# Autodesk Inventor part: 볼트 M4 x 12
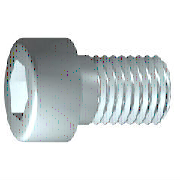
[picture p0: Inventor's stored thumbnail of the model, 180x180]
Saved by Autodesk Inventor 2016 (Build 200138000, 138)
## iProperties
IsCustomPart: 1
Created: 2012-02
Part Number: 볼트 M4 x 12
Material: 스테인리스강
Description: 6각 소켓 머리 캡 나사
Document SubType Name: Modeling
Standard: ISO 4762
Designer: mduedu
Standard Revision: Fourth edition 2004-03-01
Standards Organization: ISO
Language: ko-KR
Size Designation: M4 x 12
Categories: <MemberInstance><Categories><Category DisplayName="조임쇠" InternalName="e4da775c-781d-43d5-af7c-5136215cf5a6" Mnemonic="FSTN"><Category DisplayName="볼트" InternalN
Density: 8.08 g/cm^3
Appearance: 반광택
Author: mduedu
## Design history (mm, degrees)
sketch "스케치1"
  geometry: L1 (-1, 0)-(12, 0); L2 (12, 0)-(12, 2); L3 (12, 2)-(1.75, 2); L4 (1.75, 2)-(1.32, 2); L5 (1.32, 2)-(0, 2); L6 (0, 2)-(0, 3.5); L7 (0, 3.5)-(-4, 3.5); L8 (-4, 3.5)-(-4, 1.732); L9 (-4, 1.732)-(-2, 1.732); L10 (-2, 1.732)-(-1, 0); L11 (-7.2, 0)-(15.2, 0) reference; L12 (0, -0.7)-(0, 4.2) reference; L13 (1.75, 2)-(0, 2)
  constraints: 22 end point, 6 parallel, 2 collinear, 2 perpendicular, 1 horizontal, 1 point on line
  dimensions: "d1" = 10.25 distance from line of L3.end L2 (= GEL); "d2" = 0.42952 distance of L4.end L3.end (computed from GAL); "d3" = 4 distance between parallel lines of L8 L6 (= KOH); "d4" = 2 distance of L8.end L9.end (= INTI); "d5" = 60 deg angle of L10 L1; "d6" = 4 diameter of L3 L1 (= GD); "d7" = 4 diameter of L5 L1 (= BDM); "d8" = 3.4641 diameter of L9 L1 (= 1.1547 x SW); "d9" = 7 diameter of L7 L1 (= KOD); "d26" = 12 distance between parallel lines of L12 L2 (= NLG)
revolve "본체" sketch "스케치1" stored, may be unused: angle "d10" = 90 deg
sketch "스케치2"
  geometry: L1 (0, -4.9)-(0, 4.9) reference; L2 (-4.9, 0)-(4.9, 0) reference; L3 (1.732, 0)-(0.866, -1.5); L4 (0.866, -1.5)-(-0.866, -1.5); L5 (-0.866, -1.5)-(-1.732, 0); L6 (-1.732, 0)-(-0.866, 1.5); L7 (-0.866, 1.5)-(0.866, 1.5); L8 (0.866, 1.5)-(1.732, 0); 2 further points
  constraints: 12 end point, 1 coincident, 1 horizontal alignment, 1 point on line, 12 other
extrude "슬롯" join sketch "스케치2" stored distance "d11" = 10; taper "d12" = 0 deg
workplane "Work Plane1"
fillet "Fillet2" dims "d30" = 0.1 (= R)
body "Solid1"
fillet "모깎기1" dims "d17" = 0.4 (= RR)
feature "스레드" dims "d13" = 10.25 (= GEL), "d14" = 0
chamfer "모따기1" distance "d15" = 0.42941 (= -0.5 x SPD + 0.5 x GD); stored, may be unused: second distance "d16" = 0.42941 (= GUL), angle "d27" = 45 deg
other parameters: "GD" = 4 [user parameter; used in 2 equation terms], "NLG" = 12 [user parameter; used in 1 equation term], "GEL" = 10.25 [user parameter; used in 2 equation terms], "KOD" = 7 [user parameter; used in 1 equation term], "KOH" = 4 [user parameter; used in 1 equation term], "INTI" = 2 [user parameter; used in 1 equation term], "GAL" = 0.42941 (= 0.61345 x PTC) [user parameter; used in 1 equation term], "GUL" = 0.42941 (= 0.61345 x PTC) [user parameter; used in 1 equation term], "BDM" = 4 (= NND) [user parameter; used in 1 equation term], "SW" = 3 [user parameter; used in 2 equation terms], "RR" = 0.4 [user parameter; used in 1 equation term], "SPD" = 3.14117 (= NND - 1.2269 x PTC) [user parameter; used in 1 equation term], "d19" = 0, "d28" = 0, "d29" = 0, "R" = 0.1 [user parameter; used in 1 equation term], "TOA" = 30 deg [user parameter], "GD1" = 3.14117 (= THREADDIA - 1.2269 x PTC) [user parameter], "THREADDIA" = 4 [user parameter; used in 1 equation term], "FAWI" = 45 deg [user parameter], "TPU" = 14.28571 (computed from PTC) [user parameter], "PTC" = 0.7 [user parameter; used in 5 equation terms], "NND" = 4 [user parameter; used in 2 equation terms], "E0" = 3.465 (= 1.155 x SW) [user parameter]
